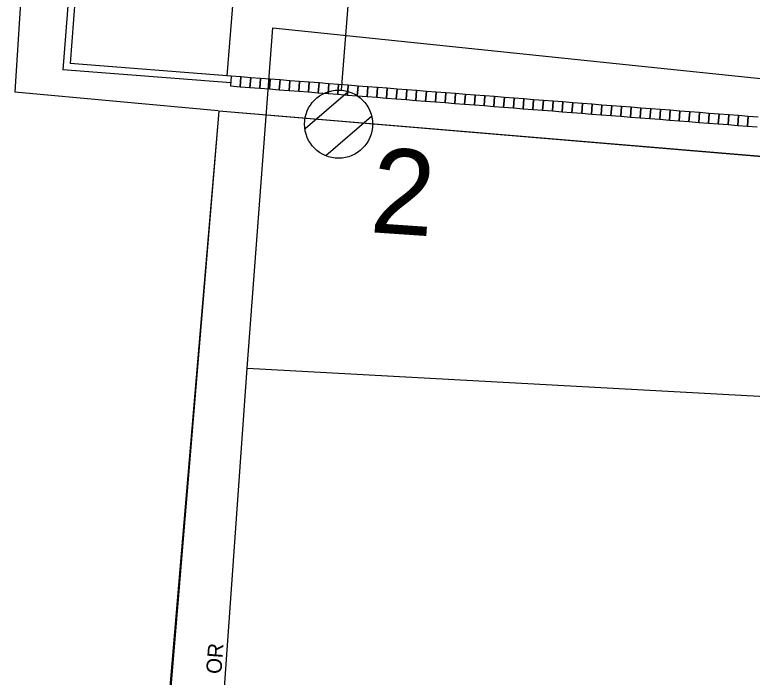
# Model space of a CAD drawing. Extents: x -670359 to -668019, y -978807 to -976674.
# Drawn here: x -669520.16 to -669511.49, y -977153.43 to -977145.65 of the extents above; entities that cross this region are included whole.
import ezdxf

# ---------------------------------------------------------------- set-up
doc = ezdxf.new("R2010")
doc.units = 0
for name, color, linetype in [('Hranice parcel', 7, 'Continuous'), ('SO 01-86-01', 7, 'Continuous'), ('SO 11-12-01', 7, 'Continuous'), ('Vnitřní kresba', 7, 'Continuous')]:
    doc.layers.add(name, color=color, linetype=linetype)

# ---------------------------------------------------------------- blocks, each defined once
blk = doc.blocks.new('POINT_DISPLAY')
blk.add_line((0, 0), (0, 0))

msp = doc.modelspace()

# ---------------------------------------------------------------- linework, layer by layer
at = {"layer": 'Hranice parcel'}
for points in [[(-669517.43, -977149.8), (-669517.13, -977145.8)], [(-669517.13, -977145.8), (-669502.57, -977147.31)], [(-669518.24, -977161.23), (-669517.43, -977149.8)]]:
    msp.add_lwpolyline(points, dxfattribs=at)
at = {"layer": 'SO 01-86-01'}
for p, q in [((-669520.0136, -977144.2951), (-669520.1621, -977146.5512)), ((-669516.2089, -977145.0374), (-669516.3254, -977146.5329)), ((-669520.1621, -977146.5512), (-669517.7721, -977146.7709)), ((-669516.7504, -977146.9812), (-669516.2464, -977146.55)), ((-669517.7634, -977146.7798), (-669518.5201, -977155.7072)), ((-669517.7634, -977146.7798), (-669518.507, -977155.6986)), ((-669517.7634, -977146.7798), (-669518.4242, -977154.5617)), ((-669445.3413, -977152.8572), (-669517.7634, -977146.7798)), ((-669445.3413, -977152.8572), (-669517.7634, -977146.7798)), ((-669443.4846, -977152.9759), (-669517.7634, -977146.7798)), ((-669516.5063, -977147.2981), (-669515.969, -977146.8384))]:
    msp.add_line(p, q, dxfattribs=at)
msp.add_circle((-669516.3564, -977146.9316), 0.4, dxfattribs=at)
at = {"layer": 'SO 11-12-01'}
for p, q in [((-669519.3953, -977143.6871), (-669519.5981, -977146.2932)), ((-669519.3155, -977143.6933), (-669519.5121, -977146.2196)), ((-669517.5396, -977144.7171), (-669517.6677, -977146.3632)), ((-669517.6179, -977146.3671), (-669519.5121, -977146.2196)), ((-669517.6241, -977146.4468), (-669519.5981, -977146.2932)), ((-669517.6179, -977146.3671), (-669517.6268, -977146.4817)), ((-669517.5032, -977146.376), (-669517.6179, -977146.3671)), ((-669517.5032, -977146.376), (-669517.5122, -977146.4907)), ((-669517.5122, -977146.4907), (-669517.5032, -977146.376)), ((-669517.3886, -977146.3849), (-669517.5032, -977146.376)), ((-669517.3886, -977146.3849), (-669517.3975, -977146.4996)), ((-669517.3975, -977146.4996), (-669517.3886, -977146.3849)), ((-669517.2739, -977146.3939), (-669517.3886, -977146.3849)), ((-669517.2739, -977146.3939), (-669517.2828, -977146.5085)), ((-669517.2828, -977146.5085), (-669517.2739, -977146.3939)), ((-669517.1593, -977146.4028), (-669517.2739, -977146.3939)), ((-669517.1593, -977146.4028), (-669517.1682, -977146.5174)), ((-669517.1682, -977146.5174), (-669517.1593, -977146.4028)), ((-669517.0446, -977146.4117), (-669517.1593, -977146.4028)), ((-669517.0446, -977146.4117), (-669517.0535, -977146.5264)), ((-669517.0535, -977146.5264), (-669517.0446, -977146.4117)), ((-669516.93, -977146.4206), (-669517.0446, -977146.4117)), ((-669516.9389, -977146.5353), (-669516.93, -977146.4206)), ((-669516.93, -977146.4206), (-669516.9389, -977146.5353)), ((-669516.8153, -977146.4296), (-669516.93, -977146.4206)), ((-669516.8242, -977146.5442), (-669516.8153, -977146.4296)), ((-669516.8153, -977146.4296), (-669516.8242, -977146.5442)), ((-669516.7007, -977146.4385), (-669516.8153, -977146.4296)), ((-669516.7096, -977146.5531), (-669516.7007, -977146.4385)), ((-669516.7007, -977146.4385), (-669516.7096, -977146.5531)), ((-669516.586, -977146.4474), (-669516.7007, -977146.4385)), ((-669516.5949, -977146.5621), (-669516.586, -977146.4474)), ((-669516.586, -977146.4474), (-669516.5949, -977146.5621)), ((-669516.4713, -977146.4563), (-669516.586, -977146.4474)), ((-669516.4803, -977146.571), (-669516.4713, -977146.4563)), ((-669516.4713, -977146.4563), (-669516.4803, -977146.571)), ((-669516.3567, -977146.4653), (-669516.4713, -977146.4563)), ((-669516.3656, -977146.5799), (-669516.3567, -977146.4653)), ((-669516.3567, -977146.4653), (-669516.3656, -977146.5799)), ((-669516.242, -977146.4742), (-669516.3567, -977146.4653)), ((-669517.6268, -977146.4817), (-669517.5122, -977146.4907)), ((-669517.5122, -977146.4907), (-669517.3975, -977146.4996)), ((-669517.3975, -977146.4996), (-669517.2828, -977146.5085)), ((-669517.2828, -977146.5085), (-669517.1682, -977146.5174)), ((-669517.1682, -977146.5174), (-669517.0535, -977146.5264)), ((-669517.0535, -977146.5264), (-669516.9389, -977146.5353)), ((-669516.9389, -977146.5353), (-669516.8242, -977146.5442)), ((-669516.8242, -977146.5442), (-669516.7096, -977146.5531)), ((-669516.251, -977146.5888), (-669516.242, -977146.4742)), ((-669516.242, -977146.4742), (-669516.251, -977146.5888)), ((-669516.1274, -977146.4831), (-669516.242, -977146.4742)), ((-669516.1363, -977146.5978), (-669516.1274, -977146.4831)), ((-669516.1274, -977146.4831), (-669516.1363, -977146.5978)), ((-669516.0127, -977146.492), (-669516.1274, -977146.4831)), ((-669516.0217, -977146.6067), (-669516.0127, -977146.492)), ((-669516.0127, -977146.492), (-669516.0217, -977146.6067)), ((-669515.8981, -977146.501), (-669516.0127, -977146.492)), ((-669515.907, -977146.6156), (-669515.8981, -977146.501)), ((-669515.8981, -977146.501), (-669515.907, -977146.6156)), ((-669515.7834, -977146.5099), (-669515.8981, -977146.501)), ((-669515.7924, -977146.6245), (-669515.7834, -977146.5099)), ((-669515.7834, -977146.5099), (-669515.7924, -977146.6245)), ((-669515.6688, -977146.5188), (-669515.7834, -977146.5099)), ((-669515.6777, -977146.6335), (-669515.6688, -977146.5188)), ((-669515.6688, -977146.5188), (-669515.6777, -977146.6335)), ((-669515.5541, -977146.5277), (-669515.6688, -977146.5188)), ((-669515.563, -977146.6424), (-669515.5541, -977146.5277)), ((-669515.5541, -977146.5277), (-669515.563, -977146.6424)), ((-669515.4395, -977146.5367), (-669515.5541, -977146.5277)), ((-669515.4484, -977146.6513), (-669515.4395, -977146.5367)), ((-669515.4395, -977146.5367), (-669515.4484, -977146.6513)), ((-669515.3248, -977146.5456), (-669515.4395, -977146.5367)), ((-669515.3337, -977146.6602), (-669515.3248, -977146.5456)), ((-669515.3248, -977146.5456), (-669515.3337, -977146.6602)), ((-669515.2102, -977146.5545), (-669515.3248, -977146.5456)), ((-669516.7096, -977146.5531), (-669516.5949, -977146.5621)), ((-669516.5949, -977146.5621), (-669516.4803, -977146.571)), ((-669516.4803, -977146.571), (-669516.3656, -977146.5799)), ((-669516.3656, -977146.5799), (-669516.251, -977146.5888)), ((-669516.251, -977146.5888), (-669516.1363, -977146.5978)), ((-669516.1363, -977146.5978), (-669516.0217, -977146.6067)), ((-669516.0217, -977146.6067), (-669515.907, -977146.6156)), ((-669515.907, -977146.6156), (-669515.7924, -977146.6245)), ((-669515.7924, -977146.6245), (-669515.6777, -977146.6335)), ((-669515.6777, -977146.6335), (-669515.563, -977146.6424)), ((-669515.2191, -977146.6692), (-669515.2102, -977146.5545)), ((-669515.2102, -977146.5545), (-669515.2191, -977146.6692)), ((-669515.0955, -977146.5634), (-669515.2102, -977146.5545)), ((-669515.1044, -977146.6781), (-669515.0955, -977146.5634)), ((-669515.0955, -977146.5634), (-669515.1044, -977146.6781)), ((-669514.9809, -977146.5724), (-669515.0955, -977146.5634)), ((-669514.9898, -977146.687), (-669514.9809, -977146.5724)), ((-669514.9809, -977146.5724), (-669514.9898, -977146.687)), ((-669514.8662, -977146.5813), (-669514.9809, -977146.5724)), ((-669514.8751, -977146.6959), (-669514.8662, -977146.5813)), ((-669514.8662, -977146.5813), (-669514.8751, -977146.6959)), ((-669514.7515, -977146.5902), (-669514.8662, -977146.5813)), ((-669514.7605, -977146.7049), (-669514.7515, -977146.5902)), ((-669514.7515, -977146.5902), (-669514.7605, -977146.7049)), ((-669514.6369, -977146.5991), (-669514.7515, -977146.5902)), ((-669514.6458, -977146.7138), (-669514.6369, -977146.5991)), ((-669514.6369, -977146.5991), (-669514.6458, -977146.7138)), ((-669514.5222, -977146.6081), (-669514.6369, -977146.5991)), ((-669514.5312, -977146.7227), (-669514.5222, -977146.6081)), ((-669514.5222, -977146.6081), (-669514.5312, -977146.7227)), ((-669514.4076, -977146.617), (-669514.5222, -977146.6081)), ((-669514.4165, -977146.7316), (-669514.4076, -977146.617)), ((-669514.4076, -977146.617), (-669514.4165, -977146.7316)), ((-669514.2929, -977146.6259), (-669514.4076, -977146.617)), ((-669514.3019, -977146.7406), (-669514.2929, -977146.6259)), ((-669514.2929, -977146.6259), (-669514.3019, -977146.7406)), ((-669514.1783, -977146.6348), (-669514.2929, -977146.6259)), ((-669514.1872, -977146.7495), (-669514.1783, -977146.6348)), ((-669514.1783, -977146.6348), (-669514.1872, -977146.7495)), ((-669514.0636, -977146.6438), (-669514.1783, -977146.6348)), ((-669515.563, -977146.6424), (-669515.4484, -977146.6513)), ((-669515.4484, -977146.6513), (-669515.3337, -977146.6602)), ((-669515.3337, -977146.6602), (-669515.2191, -977146.6692)), ((-669515.2191, -977146.6692), (-669515.1044, -977146.6781)), ((-669515.1044, -977146.6781), (-669514.9898, -977146.687)), ((-669514.9898, -977146.687), (-669514.8751, -977146.6959)), ((-669514.8751, -977146.6959), (-669514.7605, -977146.7049)), ((-669514.7605, -977146.7049), (-669514.6458, -977146.7138)), ((-669514.6458, -977146.7138), (-669514.5312, -977146.7227)), ((-669514.5312, -977146.7227), (-669514.4165, -977146.7316)), ((-669514.0726, -977146.7584), (-669514.0636, -977146.6438)), ((-669514.0636, -977146.6438), (-669514.0726, -977146.7584)), ((-669513.949, -977146.6527), (-669514.0636, -977146.6438)), ((-669513.9579, -977146.7673), (-669513.949, -977146.6527)), ((-669513.949, -977146.6527), (-669513.9579, -977146.7673)), ((-669513.8343, -977146.6616), (-669513.949, -977146.6527)), ((-669513.8432, -977146.7763), (-669513.8343, -977146.6616)), ((-669513.8343, -977146.6616), (-669513.8432, -977146.7763)), ((-669513.7197, -977146.6705), (-669513.8343, -977146.6616)), ((-669513.7286, -977146.7852), (-669513.7197, -977146.6705)), ((-669513.7197, -977146.6705), (-669513.7286, -977146.7852)), ((-669513.605, -977146.6795), (-669513.7197, -977146.6705)), ((-669513.6139, -977146.7941), (-669513.605, -977146.6795)), ((-669513.605, -977146.6795), (-669513.6139, -977146.7941)), ((-669513.4904, -977146.6884), (-669513.605, -977146.6795)), ((-669513.4993, -977146.803), (-669513.4904, -977146.6884)), ((-669513.4904, -977146.6884), (-669513.4993, -977146.803)), ((-669513.3757, -977146.6973), (-669513.4904, -977146.6884)), ((-669513.3846, -977146.812), (-669513.3757, -977146.6973)), ((-669513.3757, -977146.6973), (-669513.3846, -977146.812)), ((-669513.2611, -977146.7062), (-669513.3757, -977146.6973)), ((-669513.27, -977146.8209), (-669513.2611, -977146.7062)), ((-669513.2611, -977146.7062), (-669513.27, -977146.8209)), ((-669513.1464, -977146.7152), (-669513.2611, -977146.7062)), ((-669513.1553, -977146.8298), (-669513.1464, -977146.7152)), ((-669513.1464, -977146.7152), (-669513.1553, -977146.8298)), ((-669513.0318, -977146.7241), (-669513.1464, -977146.7152)), ((-669513.0407, -977146.8387), (-669513.0318, -977146.7241)), ((-669513.0318, -977146.7241), (-669513.0407, -977146.8387)), ((-669512.9171, -977146.733), (-669513.0318, -977146.7241)), ((-669514.4165, -977146.7316), (-669514.3019, -977146.7406)), ((-669514.3019, -977146.7406), (-669514.1872, -977146.7495)), ((-669514.1872, -977146.7495), (-669514.0726, -977146.7584)), ((-669514.0726, -977146.7584), (-669513.9579, -977146.7673)), ((-669513.9579, -977146.7673), (-669513.8432, -977146.7763)), ((-669513.8432, -977146.7763), (-669513.7286, -977146.7852)), ((-669513.7286, -977146.7852), (-669513.6139, -977146.7941)), ((-669513.6139, -977146.7941), (-669513.4993, -977146.803)), ((-669513.4993, -977146.803), (-669513.3846, -977146.812)), ((-669513.3846, -977146.812), (-669513.27, -977146.8209)), ((-669512.926, -977146.8477), (-669512.9171, -977146.733)), ((-669512.9171, -977146.733), (-669512.926, -977146.8477)), ((-669512.8024, -977146.7419), (-669512.9171, -977146.733)), ((-669512.8114, -977146.8566), (-669512.8024, -977146.7419)), ((-669512.8024, -977146.7419), (-669512.8114, -977146.8566)), ((-669512.6878, -977146.7509), (-669512.8024, -977146.7419)), ((-669512.6967, -977146.8655), (-669512.6878, -977146.7509)), ((-669512.6878, -977146.7509), (-669512.6967, -977146.8655)), ((-669512.5731, -977146.7598), (-669512.6878, -977146.7509)), ((-669512.5821, -977146.8744), (-669512.5731, -977146.7598)), ((-669512.5731, -977146.7598), (-669512.5821, -977146.8744)), ((-669512.4585, -977146.7687), (-669512.5731, -977146.7598)), ((-669512.4674, -977146.8834), (-669512.4585, -977146.7687)), ((-669512.4585, -977146.7687), (-669512.4674, -977146.8834)), ((-669512.3438, -977146.7776), (-669512.4585, -977146.7687)), ((-669512.3528, -977146.8923), (-669512.3438, -977146.7776)), ((-669512.3438, -977146.7776), (-669512.3528, -977146.8923)), ((-669512.2292, -977146.7865), (-669512.3438, -977146.7776)), ((-669512.2381, -977146.9012), (-669512.2292, -977146.7865)), ((-669512.2292, -977146.7865), (-669512.2381, -977146.9012)), ((-669512.1145, -977146.7955), (-669512.2292, -977146.7865)), ((-669512.1235, -977146.9101), (-669512.1145, -977146.7955)), ((-669512.1145, -977146.7955), (-669512.1235, -977146.9101)), ((-669511.9999, -977146.8044), (-669512.1145, -977146.7955)), ((-669512.0088, -977146.9191), (-669511.9999, -977146.8044)), ((-669511.9999, -977146.8044), (-669512.0088, -977146.9191)), ((-669511.8852, -977146.8133), (-669511.9999, -977146.8044)), ((-669513.27, -977146.8209), (-669513.1553, -977146.8298)), ((-669513.1553, -977146.8298), (-669513.0407, -977146.8387)), ((-669513.0407, -977146.8387), (-669512.926, -977146.8477)), ((-669512.926, -977146.8477), (-669512.8114, -977146.8566)), ((-669512.8114, -977146.8566), (-669512.6967, -977146.8655)), ((-669512.6967, -977146.8655), (-669512.5821, -977146.8744)), ((-669512.5821, -977146.8744), (-669512.4674, -977146.8834)), ((-669512.4674, -977146.8834), (-669512.3528, -977146.8923)), ((-669512.3528, -977146.8923), (-669512.2381, -977146.9012)), ((-669511.8941, -977146.928), (-669511.8852, -977146.8133)), ((-669511.8852, -977146.8133), (-669511.8941, -977146.928)), ((-669511.7706, -977146.8222), (-669511.8852, -977146.8133)), ((-669511.7795, -977146.9369), (-669511.7706, -977146.8222)), ((-669511.7706, -977146.8222), (-669511.7795, -977146.9369)), ((-669511.6559, -977146.8312), (-669511.7706, -977146.8222)), ((-669511.6648, -977146.9458), (-669511.6559, -977146.8312)), ((-669511.6559, -977146.8312), (-669511.6648, -977146.9458)), ((-669511.5413, -977146.8401), (-669511.6559, -977146.8312)), ((-669511.5502, -977146.9548), (-669511.5413, -977146.8401)), ((-669511.5413, -977146.8401), (-669511.5502, -977146.9548)), ((-669511.4266, -977146.849), (-669511.5413, -977146.8401)), ((-669512.2381, -977146.9012), (-669512.1235, -977146.9101)), ((-669512.1235, -977146.9101), (-669512.0088, -977146.9191)), ((-669512.0088, -977146.9191), (-669511.8941, -977146.928)), ((-669511.8941, -977146.928), (-669511.7795, -977146.9369)), ((-669511.7795, -977146.9369), (-669511.6648, -977146.9458)), ((-669511.6648, -977146.9458), (-669511.5502, -977146.9548)), ((-669511.5502, -977146.9548), (-669511.4355, -977146.9637))]:
    msp.add_line(p, q, dxfattribs=at)
at = {"layer": 'Vnitřní kresba'}
msp.add_lwpolyline([(-669517.43, -977149.8), (-669502.95, -977150.59)], dxfattribs=at)

# ---------------------------------------------------------------- block references
at = {"layer": 'SO 01-86-01', "rotation": -4.450857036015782}
msp.add_blockref('POINT_DISPLAY', (-669516.3564, -977146.9316), dxfattribs=at)

# ---------------------------------------------------------------- texts
at = {"layer": 'SO 01-86-01'}
for s, height, rotation, p in [('2', 1, 356.1, (-669516, -977148.2)), ('OR', 0.18, 85.67422, (-669517.7348, -977153.3985))]:
    msp.add_text(s, height=height, rotation=rotation, dxfattribs=at).set_placement(p)

doc.saveas('drawing.dxf')
